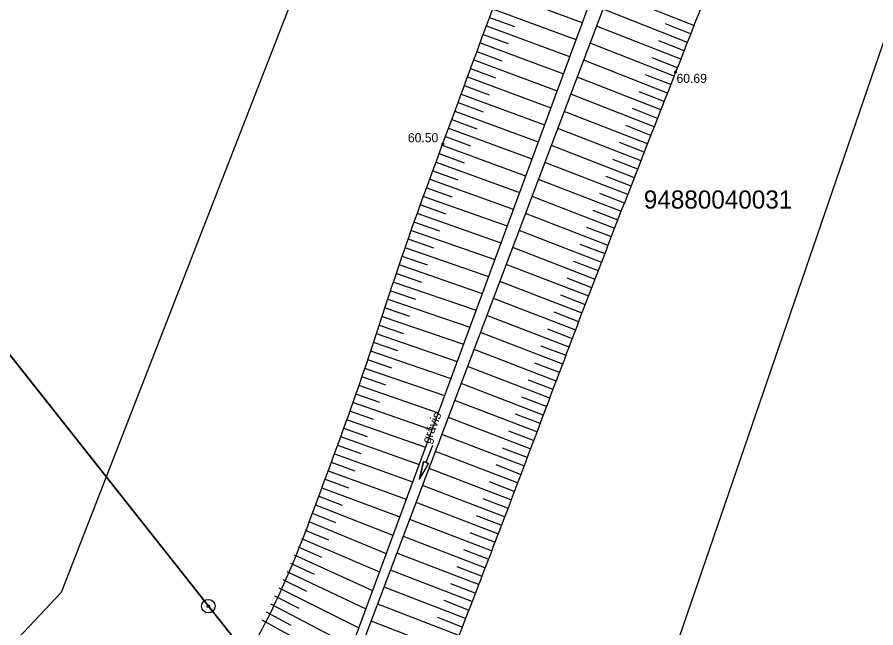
# Model space of a CAD drawing. Extents: x 616607 to 617499, y 408385 to 409695.
# Drawn here: x 617070.38 to 617117.69, y 408764.2 to 408797.83 of the extents above; entities that cross this region are included whole.
import ezdxf

# ---------------------------------------------------------------- set-up
doc = ezdxf.new("R2010")
doc.units = 0
for name, color, linetype in [('HIDG_ELEM_####_####_#', 7, 'Continuous'), ('HIDG_GRAV_####_####_#', 7, 'Continuous'), ('HIDG_GRAV_####_TKST_#', 7, 'Continuous'), ('RAMI_UZMR_####_####_#', 7, 'Continuous'), ('RELJ_AATZ_####_TKST_#', 7, 'Continuous'), ('RELJ_ELEM_####_####_#', 7, 'Continuous'), ('RELJ_NOGA_####_####_#', 7, 'Continuous'), ('ROBZ_IERR_####_####_#', 7, 'Continuous'), ('ROBZ_IERR_####_TKST_#', 7, 'Continuous'), ('ROBZ_ROBP_####_####_#', 7, 'Continuous')]:
    doc.layers.add(name, color=color, linetype=linetype)

# ---------------------------------------------------------------- blocks, each defined once
blk = doc.blocks.new('PKT')
at = {"layer": 'RELJ_ELEM_####_####_#'}
blk.add_circle((0, 0), 0.05, dxfattribs=at)
blk = doc.blocks.new('UDTEC')
at = {"layer": 'HIDG_ELEM_####_####_#'}
for p, q in [((0, 0), (1, 0)), ((1, -0.15), (1, 0.15)), ((1, 0.15), (2, 0)), ((2, 0), (1, -0.15))]:
    blk.add_line(p, q, dxfattribs=at)
blk.add_lwpolyline([(1, 0), (1, -0.15), (2, 0), (1, 0.15)], close=True, dxfattribs=at)
blk = doc.blocks.new('KUPICA')
at = {"layer": 'ROBZ_ROBP_####_####_#'}
for radius in [0.375, 0.0702, 0.0702]:
    blk.add_circle((0, 0), radius, dxfattribs=at)

msp = doc.modelspace()

# ---------------------------------------------------------------- linework, layer by layer
at = {"layer": 'HIDG_GRAV_####_####_#'}
msp.add_lwpolyline([(616957.708, 408604.801), (616964.717, 408618.582), (616997.814, 408672.816), (617082.506, 408751.106), (617088.497, 408760.889), (617116.937, 408835.934), (617137.451, 408884.548), (617152.78, 408924.733), (617163.79, 408955.542), (617160.997, 408956.152), (617115.742, 408836.043), (617088.001, 408760.943), (617081.506, 408751.106), (616997.147, 408673.705), (616963.717, 408618.582), (616956.708, 408604.801)], dxfattribs=at)
at = {"layer": 'RAMI_UZMR_####_####_#'}
for points in [[(617191.828, 409115.62), (617145.545, 408952.8), (617072.809, 408766.141), (616965.332, 408652.076), (616939.432, 408594.661), (616924.839, 408592.467), (616706.433, 408526.081), (616666.426, 408467.691)], [(616666.426, 408467.691), (616675.529, 408457.882), (616687.228, 408463.356), (616723.888, 408465.775), (616753.554, 408507.232), (616948.282, 408568.831), (616981.528, 408608.531), (617014.563, 408672.892), (617101.571, 408748.246), (617213.472, 409074.039)]]:
    msp.add_lwpolyline(points, dxfattribs=at)
at = {"layer": 'RELJ_NOGA_####_####_#'}
for p, q in [((617096.926, 408799.224), (617101.516, 408797.53)), ((617107.675, 408797.37), (617103.017, 408799.204)), ((617096.58, 408798.286), (617101.169, 408796.592)), ((617107.308, 408796.44), (617102.663, 408798.267)), ((617096.407, 408797.817), (617097.784, 408797.308)), ((617096.234, 408797.348), (617100.822, 408795.653)), ((617096.351, 408797.664), (617096.352, 408797.664)), ((617106.942, 408795.509), (617102.308, 408797.332)), ((617107.491, 408796.905), (617106.096, 408797.454)), ((617096.06, 408796.879), (617097.437, 408796.37)), ((617096.177, 408797.195), (617096.178, 408797.195)), ((617095.887, 408796.41), (617100.476, 408794.714)), ((617096.004, 408796.726), (617096.005, 408796.726)), ((617106.576, 408794.579), (617101.953, 408796.394)), ((617107.125, 408795.975), (617105.733, 408796.522)), ((617095.714, 408795.941), (617097.09, 408795.432)), ((617095.831, 408796.257), (617095.831, 408796.257)), ((617095.541, 408795.472), (617100.129, 408793.776)), ((617095.658, 408795.788), (617095.659, 408795.788)), ((617106.211, 408793.648), (617101.596, 408795.454)), ((617106.759, 408795.044), (617105.371, 408795.59)), ((617095.367, 408795.003), (617096.744, 408794.494)), ((617095.484, 408795.319), (617095.485, 408795.319)), ((617095.194, 408794.534), (617099.782, 408792.837)), ((617095.311, 408794.85), (617095.312, 408794.85)), ((617105.846, 408792.717), (617101.242, 408794.519)), ((617106.393, 408794.113), (617105.008, 408794.657)), ((617095.02, 408794.065), (617096.397, 408793.556)), ((617095.138, 408794.381), (617095.138, 408794.381)), ((617094.847, 408793.596), (617099.436, 408791.899)), ((617094.964, 408793.912), (617094.965, 408793.912)), ((617105.482, 408791.785), (617100.886, 408793.58)), ((617106.028, 408793.182), (617104.646, 408793.724)), ((617094.673, 408793.127), (617096.05, 408792.618)), ((617094.791, 408793.444), (617094.791, 408793.443)), ((617094.5, 408792.658), (617099.089, 408790.96)), ((617094.617, 408792.975), (617094.618, 408792.974)), ((617105.119, 408790.853), (617100.53, 408792.641)), ((617105.664, 408792.251), (617104.284, 408792.79)), ((617094.326, 408792.189), (617095.703, 408791.679)), ((617094.444, 408792.506), (617094.444, 408792.506)), ((617094.153, 408791.72), (617098.742, 408790.021)), ((617094.27, 408792.037), (617094.271, 408792.036)), ((617104.757, 408789.921), (617100.175, 408791.702)), ((617105.301, 408791.319), (617103.923, 408791.856)), ((617093.979, 408791.251), (617095.356, 408790.741)), ((617094.096, 408791.568), (617094.097, 408791.568)), ((617093.806, 408790.782), (617098.397, 408789.087)), ((617093.923, 408791.099), (617093.924, 408791.099)), ((617104.395, 408788.989), (617099.819, 408790.764)), ((617104.938, 408790.388), (617103.562, 408790.922)), ((617093.633, 408790.313), (617095.011, 408789.808)), ((617093.749, 408790.63), (617093.75, 408790.63)), ((617093.461, 408789.844), (617098.058, 408788.169)), ((617093.577, 408790.161), (617093.578, 408790.16)), ((617104.033, 408788.057), (617099.463, 408789.826)), ((617104.575, 408789.455), (617103.202, 408789.988)), ((617093.29, 408789.374), (617094.669, 408788.874)), ((617093.405, 408789.691), (617093.405, 408789.691)), ((617093.12, 408788.903), (617097.718, 408787.248)), ((617093.235, 408789.221), (617093.236, 408789.221)), ((617103.673, 408787.124), (617099.108, 408788.888)), ((617104.214, 408788.523), (617102.842, 408789.055)), ((617092.951, 408788.433), (617094.33, 408787.939)), ((617093.065, 408788.751), (617093.066, 408788.751)), ((617092.783, 408787.962), (617097.379, 408786.33)), ((617092.897, 408788.28), (617092.898, 408788.28)), ((617103.312, 408786.191), (617098.753, 408787.951)), ((617103.853, 408787.591), (617102.483, 408788.121)), ((617092.616, 408787.491), (617093.994, 408787.004)), ((617092.729, 408787.809), (617092.729, 408787.809)), ((617092.45, 408787.019), (617097.037, 408785.407)), ((617092.562, 408787.338), (617092.563, 408787.337)), ((617102.953, 408785.258), (617098.397, 408787.013)), ((617103.492, 408786.658), (617102.124, 408787.186)), ((617092.284, 408786.547), (617093.659, 408786.067)), ((617092.396, 408786.866), (617092.396, 408786.866)), ((617092.119, 408786.075), (617096.694, 408784.476)), ((617092.23, 408786.394), (617092.231, 408786.394)), ((617102.593, 408784.325), (617098.043, 408786.078)), ((617103.132, 408785.725), (617101.765, 408786.252)), ((617091.955, 408785.603), (617093.325, 408785.127)), ((617092.066, 408785.922), (617092.066, 408785.922)), ((617091.791, 408785.131), (617096.353, 408783.553)), ((617091.901, 408785.45), (617091.902, 408785.45)), ((617102.234, 408783.392), (617097.687, 408785.139)), ((617102.773, 408784.792), (617101.407, 408785.318)), ((617091.627, 408784.658), (617092.993, 408784.186)), ((617091.738, 408784.977), (617091.738, 408784.977)), ((617091.464, 408784.186), (617096.009, 408782.621)), ((617091.574, 408784.505), (617091.575, 408784.505)), ((617101.875, 408782.458), (617097.332, 408784.202)), ((617102.414, 408783.858), (617101.049, 408784.383)), ((617091.301, 408783.713), (617092.662, 408783.245)), ((617091.411, 408784.032), (617091.412, 408784.032)), ((617091.139, 408783.24), (617095.664, 408781.688)), ((617091.249, 408783.559), (617091.25, 408783.559)), ((617101.517, 408781.525), (617096.978, 408783.267)), ((617102.055, 408782.925), (617100.691, 408783.449)), ((617090.977, 408782.767), (617092.331, 408782.303)), ((617091.086, 408783.086), (617091.087, 408783.086)), ((617090.815, 408782.294), (617095.318, 408780.753)), ((617090.924, 408782.613), (617090.925, 408782.613)), ((617101.159, 408780.591), (617096.623, 408782.33)), ((617101.696, 408781.991), (617100.334, 408782.514)), ((617090.653, 408781.821), (617092.001, 408781.36)), ((617090.762, 408782.14), (617090.763, 408782.14)), ((617090.491, 408781.348), (617094.972, 408779.815)), ((617090.6, 408781.667), (617090.601, 408781.667)), ((617100.801, 408779.657), (617096.268, 408781.394)), ((617101.338, 408781.058), (617099.977, 408781.58)), ((617090.329, 408780.875), (617091.67, 408780.416)), ((617090.439, 408781.194), (617090.439, 408781.194)), ((617090.167, 408780.402), (617094.625, 408778.876)), ((617090.277, 408780.721), (617090.278, 408780.721)), ((617100.444, 408778.723), (617095.913, 408780.457)), ((617100.98, 408780.124), (617099.62, 408780.645)), ((617090.006, 408779.929), (617091.339, 408779.472)), ((617090.115, 408780.248), (617090.115, 408780.248)), ((617089.843, 408779.456), (617094.277, 408777.934)), ((617089.953, 408779.775), (617089.954, 408779.775)), ((617100.086, 408777.789), (617095.559, 408779.522)), ((617100.623, 408779.19), (617099.263, 408779.711)), ((617089.681, 408778.983), (617091.007, 408778.526)), ((617089.791, 408779.302), (617089.791, 408779.302)), ((617089.518, 408778.51), (617093.929, 408776.991)), ((617089.628, 408778.829), (617089.629, 408778.829)), ((617099.729, 408776.855), (617095.204, 408778.586)), ((617100.265, 408778.256), (617098.906, 408778.776)), ((617089.355, 408778.037), (617090.675, 408777.581)), ((617089.465, 408778.356), (617089.466, 408778.356)), ((617089.192, 408777.565), (617093.58, 408776.047)), ((617089.302, 408777.884), (617089.303, 408777.884)), ((617099.372, 408775.921), (617094.849, 408777.651)), ((617099.908, 408777.322), (617098.55, 408777.842)), ((617089.028, 408777.092), (617090.341, 408776.636)), ((617089.139, 408777.411), (617089.139, 408777.411)), ((617088.863, 408776.62), (617093.23, 408775.098)), ((617088.975, 408776.939), (617088.976, 408776.939)), ((617099.014, 408774.987), (617094.495, 408776.716)), ((617099.55, 408776.388), (617098.193, 408776.907)), ((617088.698, 408776.148), (617090.005, 408775.691)), ((617088.81, 408776.467), (617088.81, 408776.467)), ((617088.533, 408775.677), (617092.879, 408774.149)), ((617088.645, 408775.995), (617088.646, 408775.995)), ((617098.657, 408774.053), (617094.141, 408775.781)), ((617099.193, 408775.454), (617097.837, 408775.973)), ((617088.366, 408775.205), (617089.667, 408774.745)), ((617088.479, 408775.523), (617088.479, 408775.523)), ((617088.199, 408774.734), (617092.527, 408773.196)), ((617088.312, 408775.052), (617088.313, 408775.052)), ((617098.3, 408773.119), (617093.786, 408774.846)), ((617098.836, 408774.52), (617097.48, 408775.039)), ((617088.031, 408774.263), (617089.327, 408773.8)), ((617088.145, 408774.581), (617088.145, 408774.581)), ((617087.807, 408773.64), (617087.807, 408773.639)), ((617087.862, 408773.792), (617092.174, 408772.24)), ((617087.976, 408774.11), (617087.977, 408774.11)), ((617097.943, 408772.185), (617093.432, 408773.911)), ((617098.479, 408773.586), (617097.124, 408774.104)), ((617087.637, 408773.169), (617087.638, 408773.169)), ((617087.692, 408773.322), (617088.984, 408772.854)), ((617098.121, 408772.652), (617096.768, 408773.17)), ((617087.466, 408772.7), (617087.466, 408772.699)), ((617087.522, 408772.852), (617091.82, 408771.283)), ((617097.585, 408771.251), (617093.078, 408772.976)), ((617087.294, 408772.23), (617087.295, 408772.23)), ((617087.35, 408772.382), (617088.638, 408771.908)), ((617097.764, 408771.718), (617096.411, 408772.236)), ((617087.12, 408771.761), (617087.12, 408771.761)), ((617087.177, 408771.913), (617091.465, 408770.321)), ((617097.228, 408770.317), (617092.724, 408772.043)), ((617086.942, 408771.294), (617086.943, 408771.294)), ((617087, 408771.446), (617088.282, 408770.953)), ((617097.407, 408770.784), (617096.055, 408771.302)), ((617086.76, 408770.828), (617086.761, 408770.828)), ((617086.82, 408770.979), (617091.088, 408769.3)), ((617096.87, 408769.384), (617092.37, 408771.108)), ((617086.574, 408770.364), (617086.575, 408770.364)), ((617086.635, 408770.515), (617087.916, 408770.001)), ((617097.049, 408769.851), (617095.698, 408770.368)), ((617086.385, 408769.901), (617086.385, 408769.901)), ((617086.447, 408770.051), (617090.716, 408768.295)), ((617096.512, 408768.45), (617092.016, 408770.174)), ((617086.191, 408769.44), (617086.192, 408769.44)), ((617086.255, 408769.59), (617087.536, 408769.048)), ((617096.691, 408768.917), (617095.342, 408769.434)), ((617085.994, 408768.981), (617085.994, 408768.981)), ((617086.058, 408769.13), (617090.344, 408767.286)), ((617096.154, 408767.516), (617091.662, 408769.241)), ((617085.792, 408768.524), (617085.793, 408768.523)), ((617085.858, 408768.672), (617087.146, 408768.1)), ((617096.333, 408767.983), (617094.985, 408768.5)), ((617085.586, 408768.068), (617085.586, 408768.068)), ((617085.653, 408768.216), (617089.962, 408766.253)), ((617095.796, 408766.583), (617091.309, 408768.308)), ((617085.376, 408767.614), (617085.377, 408767.614)), ((617085.445, 408767.761), (617086.745, 408767.161)), ((617095.975, 408767.049), (617094.628, 408767.567)), ((617085.162, 408767.162), (617085.163, 408767.162)), ((617085.232, 408767.309), (617089.589, 408765.244)), ((617095.437, 408765.649), (617090.954, 408767.372)), ((617084.944, 408766.712), (617084.945, 408766.712)), ((617085.016, 408766.858), (617086.331, 408766.22)), ((617095.616, 408766.116), (617094.271, 408766.633)), ((617084.722, 408766.264), (617084.722, 408766.264)), ((617084.795, 408766.409), (617089.207, 408764.21)), ((617095.078, 408764.716), (617090.601, 408766.44)), ((617084.496, 408765.819), (617084.497, 408765.818)), ((617084.57, 408765.963), (617085.905, 408765.285)), ((617095.257, 408765.183), (617093.913, 408765.7)), ((617084.265, 408765.375), (617084.265, 408765.375)), ((617084.34, 408765.519), (617088.823, 408763.17)), ((617094.718, 408763.783), (617090.248, 408765.508)), ((617084.03, 408764.933), (617084.031, 408764.933)), ((617084.107, 408765.077), (617085.464, 408764.349)), ((617094.898, 408764.249), (617093.556, 408764.766)), ((617083.791, 408764.494), (617083.791, 408764.494)), ((617083.869, 408764.637), (617088.439, 408762.13)), ((617094.358, 408762.85), (617089.893, 408764.573))]:
    msp.add_line(p, q, dxfattribs=at)
for points in [[(616952.11, 408607.531), (616956.151, 408614.166), (616960.13, 408620.838), (616964.128, 408627.499), (616969.357, 408636.209), (616974.533, 408644.951), (616979.755, 408653.666), (616982.367, 408658.027), (616985.018, 408662.364), (616987.709, 408666.677), (616989.056, 408668.838), (616990.438, 408670.976), (616991.835, 408673.105), (616992.534, 408674.172), (616993.243, 408675.231), (616993.95, 408676.293), (616994.657, 408677.356), (616995.377, 408678.409), (616996.104, 408679.46), (616998.164, 408682.436), (617000.493, 408685.215), (617003.037, 408687.806), (617005.59, 408690.406), (617008.236, 408692.879), (617011.016, 408695.214), (617013.812, 408697.562), (617016.632, 408699.88), (617019.423, 408702.233), (617020.817, 408703.408), (617022.221, 408704.57), (617023.595, 408705.77), (617024.962, 408706.965), (617026.3, 408708.194), (617027.642, 408709.417), (617031.797, 408713.202), (617035.92, 408717.024), (617040.083, 408720.8), (617044.243, 408724.572), (617048.471, 408728.267), (617052.642, 408732.025), (617056.824, 408735.794), (617060.981, 408739.59), (617065.093, 408743.436), (617067.159, 408745.369), (617069.191, 408747.335), (617071.208, 408749.318), (617072.22, 408750.314), (617073.221, 408751.32), (617074.226, 408752.322), (617075.234, 408753.328), (617076.23, 408754.338), (617077.212, 408755.375), (617081.698, 408760.112), (617084.989, 408765.985), (617087.243, 408772.093), (617089.541, 408778.321), (617091.528, 408784.634), (617093.829, 408790.846), (617099.646, 408806.547), (617105.384, 408822.279), (617111.331, 408837.932), (617116.967, 408852.766), (617122.795, 408867.526), (617128.465, 408882.346), (617134.52, 408898.17), (617140.109, 408914.165), (617146.15, 408930), (617147.203, 408932.762), (617148.413, 408935.46), (617149.608, 408938.162), (617150.805, 408940.87), (617152.218, 408943.437), (617153.491, 408946.151), (617155.134, 408949.654), (617156.252, 408953.338), (617157.386, 408956.937), (617157.388, 408956.942), (617157.376, 408956.956), (617157.382, 408956.955), (617158.587, 408956.687), (617159.792, 408956.42), (617160.997, 408956.152)], [(617163.79, 408955.542), (617165.45, 408955.194), (617167.11, 408954.846), (617168.77, 408954.498), (617168.913, 408954.468), (617169.034, 408954.324), (617169.074, 408954.183), (617169.128, 408953.99), (617169.08, 408953.773), (617169.007, 408953.587), (617168.835, 408953.148), (617168.665, 408952.708), (617168.483, 408952.272), (617167.485, 408949.894), (617166.495, 408947.512), (617165.486, 408945.138), (617164.477, 408942.762), (617163.444, 408940.395), (617162.435, 408938.019), (617160.416, 408933.265), (617158.392, 408928.513), (617156.542, 408923.692), (617150.713, 408908.507), (617144.931, 408893.305), (617139.111, 408878.118), (617136.201, 408870.523), (617133.294, 408862.928), (617130.378, 408855.336), (617127.463, 408847.744), (617124.504, 408840.168), (617121.547, 408832.592), (617116.624, 408819.98), (617111.621, 408807.399), (617106.663, 408794.801), (617101.918, 408782.741), (617097.386, 408770.604), (617092.68, 408758.522), (617091.748, 408756.128), (617090.638, 408753.8), (617089.099, 408751.701), (617087.891, 408750.055), (617086.512, 408748.607), (617085.075, 408747.191), (617082.094, 408744.254), (617079.138, 408741.303), (617076.078, 408738.453), (617073.02, 408735.605), (617069.97, 408732.751), (617066.861, 408729.96), (617060.644, 408724.38), (617054.349, 408718.89), (617048.124, 408713.32), (617041.902, 408707.753), (617035.717, 408702.149), (617029.576, 408696.491), (617026.506, 408693.662), (617023.563, 408690.704), (617020.596, 408687.763), (617017.626, 408684.818), (617014.683, 408681.855), (617011.931, 408678.697), (617008.517, 408674.776), (617005.359, 408670.661), (617002.288, 408666.476), (616999.318, 408662.428), (616996.36, 408658.374), (616993.424, 408654.302), (616990.492, 408650.235), (616987.575, 408646.161), (616984.691, 408642.059), (616983.288, 408640.063), (616981.951, 408638.02), (616980.703, 408635.922), (616979.453, 408633.819), (616978.237, 408631.7), (616977.033, 408629.572), (616975.83, 408627.444), (616974.65, 408625.305), (616973.452, 408623.174), (616972.259, 408621.052), (616970.984, 408618.974), (616969.729, 408616.893), (616969.613, 408616.701), (616969.41, 408616.592), (616969.29, 408616.383), (616968.995, 408615.872), (616968.948, 408615.291), (616969.02, 408614.761), (616969.09, 408614.251), (616969.19, 408613.683), (616969.493, 408613.251)]]:
    msp.add_open_spline(points, degree=3, dxfattribs=at)
at = {"layer": 'ROBZ_IERR_####_####_#'}
for points in [[(617055.284, 408797.783), (617087.528, 408757.04), (616999.181, 408676.019), (616968.565, 408608.405), (616958.517, 408604.593), (616940.576, 408582.801), (616889.795, 408568.012), (616805.459, 408543.657), (616730.494, 408522.344), (616717.135, 408556.579)], [(617001.984, 408630.998), (616968.565, 408608.405), (616999.181, 408676.019), (617087.528, 408757.04), (617055.515, 408797.492)]]:
    msp.add_lwpolyline(points, dxfattribs=at)

# ---------------------------------------------------------------- block references
at = {"layer": 'HIDG_ELEM_####_####_#', "rotation": -111.04399182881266}
msp.add_blockref('UDTEC', (617093.267, 408774.247), dxfattribs=at)
at = {"layer": 'RELJ_ELEM_####_####_#'}
for p in [(617106.663, 408794.801), (617093.829, 408790.846)]:
    msp.add_blockref('PKT', p, dxfattribs=at)
at = {"layer": 'ROBZ_ROBP_####_####_#'}
msp.add_blockref('KUPICA', (617080.915, 408765.396), dxfattribs=at)

# ---------------------------------------------------------------- texts
at = {"layer": 'HIDG_GRAV_####_TKST_#'}
msp.add_text('grāvis', height=0.5, rotation=68.956, dxfattribs=at).set_placement((617093.127, 408774.301))
at = {"layer": 'RELJ_AATZ_####_TKST_#'}
for s, p in [('60.69', (617106.711, 408794.206)), ('60.50', (617091.911, 408790.941))]:
    msp.add_text(s, height=0.5, dxfattribs=at).set_placement(p)
at = {"layer": 'ROBZ_IERR_####_TKST_#'}
msp.add_text('94880040031', height=1, dxfattribs=at).set_placement((617104.91, 408787.287))

doc.saveas('drawing.dxf')
